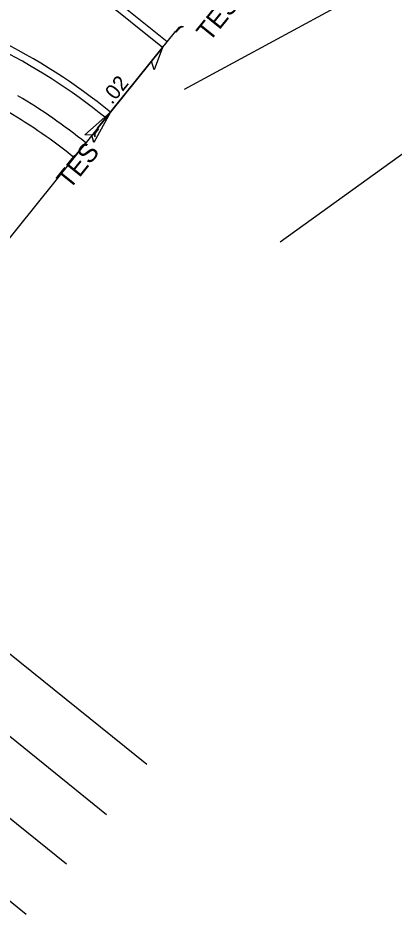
# Model space of a CAD drawing. Extents: x 1486489 to 1490134, y 497089 to 500876.
# Drawn here: x 1488744.4 to 1488844.3, y 498810.4 to 499048.4 of the extents above; entities that cross this region are included whole.
import ezdxf

# ---------------------------------------------------------------- set-up
doc = ezdxf.new("R2010")
doc.units = 0
for name, color, linetype in [('DEV PRELIMINARY STAMP CELL', 7, 'Continuous'), ('Gray Area Fill Shapes', 7, 'Continuous'), ('Prop Guardrail', 7, 'Continuous'), ('Prop Guardrail Anchor Unit CELL', 7, 'Continuous'), ('Prop Horizontal Alignment Station Label', 7, 'Continuous'), ('Scratch_Level_0', 7, 'Continuous'), ('Scratch_Level_5', 7, 'Continuous'), ('Sheet Border Standard 30in CELL', 7, 'Continuous'), ('Sheet Plan CELL', 7, 'Continuous'), ('Sheet Sticker Exception Certification CELL', 7, 'Continuous')]:
    doc.layers.add(name, color=color, linetype=linetype)

msp = doc.modelspace()

# ---------------------------------------------------------------- linework, layer by layer
at = {"layer": 'DEV PRELIMINARY STAMP CELL'}
msp.add_line((1488768.98, 499023.34), (1488782.79, 499040.47), dxfattribs=at)
msp.add_lwpolyline([(1488782.79, 499040.47), (1488780.58, 499034.54), (1488779.88, 499036.87)], close=True, dxfattribs=at)
at = {"layer": 'Prop Guardrail'}
msp.add_line((1488765.55, 499019.09), (1488786.21, 499044.72), dxfattribs=at)
at = {"layer": 'Prop Guardrail Anchor Unit CELL'}
for p, q in [((1488786.21, 499044.72), (1488786.92, 499045.59)), ((1488786.43, 499044.54), (1488787.14, 499045.42)), ((1488786.21, 499044.72), (1488786.43, 499044.54)), ((1488765.55, 499019.09), (1488764.85, 499018.22)), ((1488765.77, 499018.92), (1488765.06, 499018.04)), ((1488765.55, 499019.09), (1488765.77, 499018.92))]:
    msp.add_line(p, q, dxfattribs=at)
for centre, radius, start, end in [((1488787.88, 499044.77), 1.27, 69.0507, 139.4447), ((1488788.33, 499044.35), 1.6, 89.9907, 138.2982), ((1488765.85, 499017.45), 1.27, 142.7866, 213.1806), ((1488766.36, 499017.1), 1.6, 143.9331, 192.2406)]:
    msp.add_arc(centre, radius, start, end, dxfattribs=at)
at = {"layer": 'Prop Horizontal Alignment Station Label'}
msp.add_line((1488759.25, 499011.28), (1488762.39, 499015.17), dxfattribs=at)
for radius in [154.5, 149.5]:
    msp.add_arc((1488665.4, 498894.91), radius, 51.1156, 59.261, dxfattribs=at)
at = {"layer": 'Scratch_Level_0'}
msp.add_line((1488768.98, 499023.34), (1488665.4, 498894.91), dxfattribs=at)
msp.add_lwpolyline([(1488762.12, 499017.31), (1488768.98, 499023.34), (1488764.54, 499015.29), (1488764.02, 499017.19)], close=True, dxfattribs=at)
at = {"layer": 'Scratch_Level_5'}
for p, q in [((1488784.04, 499042.03), (1488762.85, 499059.11)), ((1488782.79, 499040.47), (1488784.04, 499042.03)), ((1488767.72, 499021.79), (1488768.98, 499023.34))]:
    msp.add_line(p, q, dxfattribs=at)
msp.add_arc((1488665.4, 498894.91), 163, 51.1156, 63.6938, dxfattribs=at)
at = {"layer": 'Sheet Border Standard 30in CELL'}
for p, q in [((1488814, 498988.85), (1489138.26, 499223.06)), ((1489140.33, 499219.78), (1488788.55, 499029.37))]:
    msp.add_line(p, q, dxfattribs=at)
at = {"layer": 'Sheet Plan CELL'}
for p, q in [((1488778.61, 498850.05), (1488467.24, 499101.15)), ((1488456.57, 499087.92), (1488767.94, 498836.82)), ((1488757.26, 498823.59), (1488445.9, 499074.69)), ((1488435.23, 499061.45), (1488746.59, 498810.35))]:
    msp.add_line(p, q, dxfattribs=at)
at = {"layer": 'Sheet Sticker Exception Certification CELL'}
for q in [(1488761.6, 499057.56), (1488768.98, 499023.34)]:
    msp.add_line((1488782.79, 499040.47), q, dxfattribs=at)
msp.add_arc((1488665.4, 498894.91), 165, 51.1156, 63.6938, dxfattribs=at)

# ---------------------------------------------------------------- texts
at = {"layer": 'Gray Area Fill Shapes'}
msp.add_text('.02', height=4, rotation=51.1156, dxfattribs=at).set_placement((1488769.36, 499025.18))
at = {"layer": 'Prop Guardrail Anchor Unit CELL'}
for p in [(1488795.27, 499041.79), (1488758.11, 499002.58)]:
    msp.add_text('TES', height=5, rotation=51.1156, dxfattribs=at).set_placement(p)

doc.saveas('drawing.dxf')
